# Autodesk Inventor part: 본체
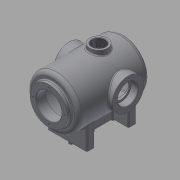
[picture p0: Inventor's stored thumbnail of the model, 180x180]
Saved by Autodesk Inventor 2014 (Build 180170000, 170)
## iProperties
Created: 2016-02
Part Number: 본체
Material: 일반
Document SubType Name: Modeling
Designer: mduedu
Density: 1 g/cm^3
Appearance: 기본값
Mass: 1183.43 g
Surface Area: 2101.15 cm^2
Volume: 1183.43 cm^3
Author: mduedu
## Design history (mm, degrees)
sketch "스케치2"
  geometry: L1 (0, 100)-(0, -100); L2 (65, -75.993)-(65, 100); L3 (65, 100)-(0, 100); A1 r 100 centre (0, 0) between (0, -100) and (65, -75.993); 2 further points
  constraints: 6 end point, 2 midpoint, 2 point on circle, 1 centre point, 1 coincident, 1 horizontal, 1 parallel, 1 vertical
  dimensions: "d3" = 200 distance of L1.start L1.end; "d5" = 130 diameter of L2 L1; "d6" = 100 radius of A1
revolve "회전1" sketch "스케치2" stored, may be unused: angle "d7" = 90 deg
sketch "스케치3"
  geometry: C1 r 47.5 at (0, 0); 1 further point
  constraints: 1 centre point, 1 coincident
  dimensions: "d8" = 95 diameter of C1
extrude "돌출2" join sketch "스케치3" distance "d10" = 10; taper "d11" = 0 deg
sketch "스케치5"
  geometry: L1 (47.5, 110)-(47.5, 100) reference; L2 (47.5, 100)-(65, 100) reference; L3 (65, 100)-(65, -75.993) reference; L4 (-65, -75.993)-(-65, 100) reference; L5 (-65, 100)-(-47.5, 100) reference; L6 (-47.5, 100)-(-47.5, 110) reference; L7 (-47.5, 110)-(47.5, 110) reference; L8 (55, 85)-(55, -71.239); L9 (0, 85)-(55, 85); L10 (0, 85)-(0, -90); A1 r 100 centre (0, 0) between (0, -100) and (65, -75.993) reference; A2 r 100 centre (0, 0) between (-65, -75.993) and (0, -100) reference; A3 r 90 centre (0, 0) between (0, -90) and (55, -71.239); 1 further point
  constraints: 6 end point, 2 point on circle, 1 centre point, 1 parallel, 1 perpendicular, 1 point on line, 1 vertical
  dimensions: "d13" = 10 distance between parallel lines of L3 L8; "d14" = 10 radial gap between concentric circles of A3 A1; "d15" = 15 distance between parallel lines of L9 L2
revolve "회전2" sketch "스케치5" stored, may be unused: angle "d16" = 90 deg
hole "구멍1" diameter "d19" = 65; stored, may be unused: countersink angle "d23" = 90 deg, drill point angle "d25" = 118 deg; dims "d17" = 10, "d18" = 10, "d20" = 6, "d21" = 4, "d22" = 2, "d24" = 8
node "작업 평면1"
sketch "스케치6"
  geometry: L1 (47.5, 110)-(-47.5, 110) reference; C1 r 40 at (0, -17); 1 further point
  constraints: 1 centre point, 1 vertical alignment
  dimensions: "d27" = 80 diameter of C1; "d29" = 127 distance from line of C1.centre L1
extrude "돌출3" join sketch "스케치6" stored distance "d30" = 10; taper "d31" = 0 deg
hole "구멍2" diameter "d34" = 42; stored, may be unused: countersink angle "d38" = 90 deg, drill point angle "d40" = 118 deg; dims "d32" = 10, "d33" = 10, "d35" = 6, "d36" = 52, "d37" = 18, "d39" = 8
sketch "스케치7" dims "d41" = 65
  geometry: C1 r 40 at (0, 0) reference; 3 further points
  constraints: 2 vertical alignment, 1 coincident, 2 other
hole "구멍3" sketch "스케치7" at (0, 32.5) diameter "d43" = 3.242; stored, may be unused: countersink angle "d47" = 90 deg, drill point angle "d49" = 118 deg; dims "d44" = 11, "d45" = 13, "d46" = 18, "d48" = 13
sketch "스케치8" dims "d53" = 80
  geometry: 3 further points
  constraints: 2 vertical alignment, 1 coincident, 2 other
hole "구멍4" sketch "스케치8" at (0, 40) diameter "d56" = 3.242; stored, may be unused: countersink angle "d60" = 90 deg, drill point angle "d62" = 118 deg; dims "d57" = 11, "d58" = 13, "d59" = 18, "d61" = 13
fillet "모깎기1" dims "d66" = 10
fillet "모깎기2" dims "d67" = 3
fillet "모깎기3" dims "d68" = 0.3
chamfer "모따기1" distance "d69" = 1; stored, may be unused: second distance "d70" = 2, angle "d71" = 45 deg
node "작업 평면5"
sketch "스케치10"
  geometry: L1 (-50, -63)-(50, -63); L2 (50, -63)-(50, -43); L3 (50, -43)-(-50, -43); L4 (-50, -43)-(-50, -63); L5 (-50, 0)-(50, 0); L6 (-50, 63)-(50, 63); L7 (50, 63)-(50, 43); L8 (50, 43)-(-50, 43); L9 (-50, 43)-(-50, 63); 2 further points
  constraints: 18 end point, 4 symmetric about line, 2 parallel, 2 perpendicular, 1 coincident, 1 horizontal, 1 midpoint
  dimensions: "d80" = 20 distance of L3.end L1.start; "d82" = 100 distance of L1.start L1.end; "d130" = 43 vertical distance of L3.end point (0, 0); "d131" = 50 horizontal distance of L3.end point (0, 0); "d132" = 100 distance of L5.start L5.end
extrude "돌출5" join sketch "스케치10" stored distance "d84" = 10; taper "d85" = 0 deg
sketch "스케치11"
  geometry: L1 (-100, -43)-(-100, 43); L2 (-65, 90)-(-65, -71.239) reference; L3 (-100, -43)-(-41.533, -43) reference; L4 (-100, 43)-(-41.533, 43) reference; 1 further point
  constraints: 2 end point, 1 point on line, 1 vertical
feature "리브1" sketch "스케치11" dims "d88" = 1, "d89" = 20, "d90" = 0, "d91" = 0, "d92" = 1, "d93" = 1
fillet "모깎기18" dims "d179" = 3
fillet "모깎기19" dims "d180" = 3
fillet "모깎기20" dims "d181" = 3
fillet "모깎기21" dims "d182" = 3
fillet "모깎기16" dims "d167" = 3
fillet "모깎기17" dims "d168" = 3
node "작업 평면6"
sketch "스케치19"
  geometry: L1 (75, -57)-(75, 23) reference; L2 (-75, -57)-(-75, 23) reference; L3 (75, -17)-(-75, -17); C1 r 22.5 at (0, -17); 1 further point
  constraints: 3 midpoint, 2 end point, 1 centre point
  dimensions: "d149" = 45 diameter of C1
extrude "돌출11" join sketch "스케치19" stored distance "d150" = 10; taper "d151" = 0 deg
hole "구멍6" diameter "d154" = 33.376; stored, may be unused: countersink angle "d158" = 90 deg, drill point angle "d160" = 118 deg; dims "d155" = 6, "d156" = 4, "d157" = 2, "d159" = 8, "d177" = 10, "d178" = 10
fillet "모깎기11" dims "d161" = 3
chamfer "모따기3" distance "d164" = 1; stored, may be unused: second distance "d165" = 2, angle "d166" = 45 deg
sketch "스케치20"
  geometry: L1 (10, 40)-(10, -40) reference; L2 (13, -43)-(47, -43) reference; L3 (-10, -40)-(-10, 40) reference; L4 (47, 43)-(13, 43) reference; L5 (-40, 53)-(40, 53); L6 (-40, -53)-(40, -53); L7 (0, 53)-(0, -53); L8 (50, -46)-(50, -60) reference; L9 (47, -63)-(-47, -63) reference; L10 (-50, -60)-(-50, -46) reference; L11 (-47, -43)-(-13, -43) reference; L12 (-13, 43)-(-47, 43) reference; L13 (-50, 46)-(-50, 60) reference; L14 (-47, 63)-(47, 63) reference; L15 (50, 60)-(50, 46) reference; C1 r 5 at (0, 53); C2 r 5 at (0, 0); C3 r 5 at (0, -53); A1 r 3 centre (13, -40) between (10, -40) and (13, -43) reference; A2 r 3 centre (-13, -40) between (-13, -43) and (-10, -40) reference; A3 r 3 centre (-13, 40) between (-10, 40) and (-13, 43) reference; A4 r 3 centre (13, 40) between (13, 43) and (10, 40) reference; A5 r 3 centre (47, -46) between (50, -46) and (47, -43) reference; A6 r 3 centre (47, -60) between (47, -63) and (50, -60) reference; A7 r 3 centre (-47, -60) between (-50, -60) and (-47, -63) reference; A8 r 3 centre (-47, -46) between (-47, -43) and (-50, -46) reference; A9 r 3 centre (-47, 46) between (-50, 46) and (-47, 43) reference; A10 r 3 centre (-47, 60) between (-47, 63) and (-50, 60) reference; A11 r 3 centre (47, 60) between (50, 60) and (47, 63) reference; A12 r 3 centre (47, 46) between (47, 43) and (50, 46) reference; 1 further point
  constraints: 6 end point, 3 centre point, 3 coincident, 2 midpoint, 2 parallel
  dimensions: "d169" = 10 diameter of C1; "d170" = 10 diameter of C2; "d171" = 10 diameter of C3
extrude "돌출12" join sketch "스케치20" distance "d172" = 10; taper "d173" = 0 deg
chamfer "모따기4" distance "d174" = 1; stored, may be unused: second distance "d175" = 2, angle "d176" = 45 deg
node "솔리드2"
pattern_circular "원형 패턴1" dims angle "d51" = 360 deg
mirror "대칭1"
pattern_circular "원형 패턴2" dims angle "d64" = 360 deg
node "절단 모서리 투영1"
node "절단 모서리 투영4"
other parameters: "d26" = 75, "d136" = 175
